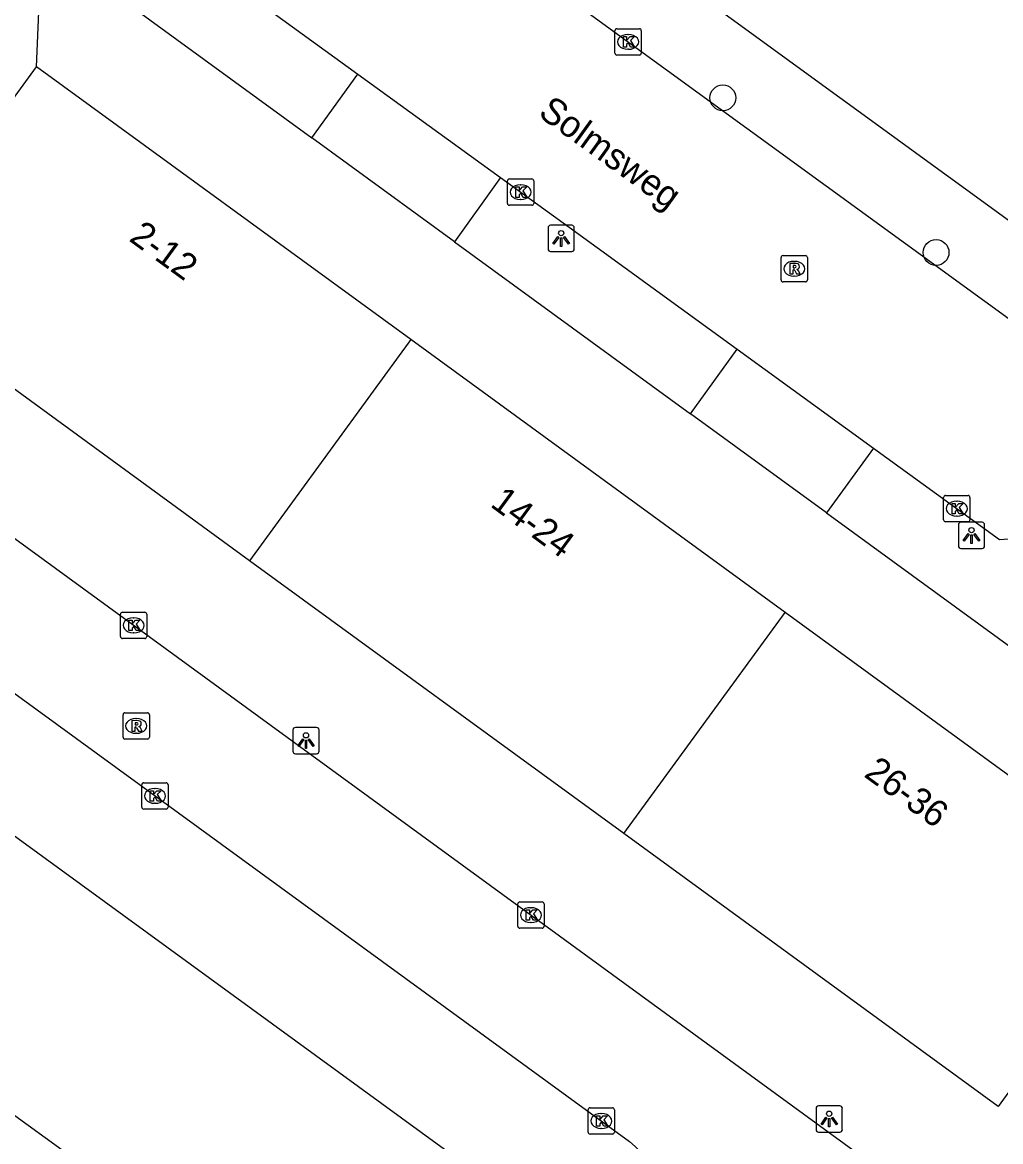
# Model space of a CAD drawing. Extents: x 159675 to 160530, y 382179 to 382901.
# Drawn here: x 160188.71 to 160225.89, y 382395.67 to 382438.2 of the extents above; entities that cross this region are included whole.
import ezdxf

# ---------------------------------------------------------------- set-up
doc = ezdxf.new("R2010")
doc.units = 0
for name, color, linetype in [('IMGEO_Boom', 7, 'Continuous'), ('IMGEO_Groenvoorziening', 7, 'Continuous'), ('IMGEO_Kolk', 7, 'Continuous'), ('IMGEO_Lichtpunt', 7, 'Continuous'), ('IMGEO_Openbare_ruimte_label', 7, 'Continuous'), ('IMGEO_Pand', 7, 'Continuous'), ('IMGEO_Pand_nummerreeks', 7, 'Continuous'), ('IMGEO_Rijbaan_lokaal_open', 7, 'Continuous'), ('IMGEO_Rioolput', 7, 'Continuous'), ('IMGEO_Voetpad_open', 7, 'Continuous')]:
    doc.layers.add(name, color=color, linetype=linetype)

msp = doc.modelspace()

# ---------------------------------------------------------------- linework, layer by layer
at = {"layer": 'IMGEO_Boom'}
for centre in [(160215.336, 382435.334), (160223.441, 382429.456)]:
    msp.add_circle(centre, 0.489, dxfattribs=at)
at = {"layer": 'IMGEO_Groenvoorziening'}
msp.add_lwpolyline([(160205.238, 382384.168), (160210.404, 382391.261), (160181.255, 382412.483)], dxfattribs=at)
at = {"layer": 'IMGEO_Kolk'}
for p, q in [((160211.237, 382437.033), (160211.237, 382437.885)), ((160211.312, 382437.959), (160212.164, 382437.959)), ((160212.238, 382437.885), (160212.238, 382437.033)), ((160211.725, 382437.739), (160211.75, 382437.739)), ((160211.748, 382437.179), (160211.723, 382437.179)), ((160212.164, 382436.959), (160211.312, 382436.959)), ((160207.149, 382431.324), (160207.149, 382432.176)), ((160207.224, 382432.25), (160208.076, 382432.25)), ((160207.637, 382432.03), (160207.662, 382432.03)), ((160208.15, 382432.176), (160208.15, 382431.324)), ((160208.076, 382431.25), (160207.224, 382431.25)), ((160207.66, 382431.47), (160207.635, 382431.47)), ((160223.728, 382419.297), (160223.728, 382420.149)), ((160223.803, 382420.223), (160224.655, 382420.223)), ((160224.729, 382420.149), (160224.729, 382419.297)), ((160224.216, 382420.003), (160224.241, 382420.003)), ((160224.655, 382419.223), (160223.803, 382419.223)), ((160224.239, 382419.443), (160224.214, 382419.443)), ((160192.517, 382415.789), (160193.369, 382415.789)), ((160192.442, 382414.863), (160192.442, 382415.715)), ((160192.93, 382415.569), (160192.955, 382415.569)), ((160193.443, 382415.715), (160193.443, 382414.863)), ((160192.953, 382415.009), (160192.928, 382415.009)), ((160193.369, 382414.789), (160192.517, 382414.789)), ((160193.251, 382408.38), (160193.251, 382409.232)), ((160193.326, 382409.306), (160194.178, 382409.306)), ((160193.739, 382409.086), (160193.764, 382409.086)), ((160194.252, 382409.232), (160194.252, 382408.38)), ((160194.178, 382408.306), (160193.326, 382408.306)), ((160193.762, 382408.526), (160193.737, 382408.526)), ((160207.619, 382404.78), (160208.471, 382404.78)), ((160207.544, 382403.854), (160207.544, 382404.706)), ((160208.032, 382404.56), (160208.057, 382404.56)), ((160208.545, 382404.706), (160208.545, 382403.854)), ((160208.055, 382404), (160208.03, 382404)), ((160208.471, 382403.78), (160207.619, 382403.78)), ((160210.216, 382396.029), (160210.216, 382396.881)), ((160210.291, 382396.955), (160211.143, 382396.955)), ((160210.704, 382396.735), (160210.729, 382396.735)), ((160211.217, 382396.881), (160211.217, 382396.029)), ((160211.143, 382395.955), (160210.291, 382395.955)), ((160210.727, 382396.175), (160210.702, 382396.175))]:
    msp.add_line(p, q, dxfattribs=at)
for points in [[(160211.237, 382437.033), (160211.237, 382437.885)], [(160211.312, 382437.959), (160212.164, 382437.959)], [(160212.238, 382437.885), (160212.238, 382437.033)], [(160211.558, 382437.659), (160211.681, 382437.659), (160211.681, 382437.508), (160211.811, 382437.659), (160211.975, 382437.659), (160211.829, 382437.508), (160211.982, 382437.259), (160211.83, 382437.259), (160211.745, 382437.423), (160211.681, 382437.356), (160211.681, 382437.259), (160211.558, 382437.259), (160211.558, 382437.659)], [(160212.164, 382436.959), (160211.312, 382436.959)], [(160207.149, 382431.324), (160207.149, 382432.176)], [(160207.224, 382432.25), (160208.076, 382432.25)], [(160207.47, 382431.95), (160207.593, 382431.95), (160207.593, 382431.799), (160207.723, 382431.95), (160207.887, 382431.95), (160207.741, 382431.799), (160207.894, 382431.55), (160207.742, 382431.55), (160207.657, 382431.714), (160207.593, 382431.647), (160207.593, 382431.55), (160207.47, 382431.55), (160207.47, 382431.95)], [(160208.15, 382432.176), (160208.15, 382431.324)], [(160208.076, 382431.25), (160207.224, 382431.25)], [(160223.728, 382419.297), (160223.728, 382420.149)], [(160223.803, 382420.223), (160224.655, 382420.223)], [(160224.729, 382420.149), (160224.729, 382419.297)], [(160224.049, 382419.923), (160224.172, 382419.923), (160224.172, 382419.772), (160224.302, 382419.923), (160224.466, 382419.923), (160224.32, 382419.772), (160224.473, 382419.523), (160224.321, 382419.523), (160224.236, 382419.687), (160224.172, 382419.62), (160224.172, 382419.523), (160224.049, 382419.523), (160224.049, 382419.923)], [(160224.655, 382419.223), (160223.803, 382419.223)], [(160192.517, 382415.789), (160193.369, 382415.789)], [(160192.442, 382414.863), (160192.442, 382415.715)], [(160192.763, 382415.489), (160192.886, 382415.489), (160192.886, 382415.338), (160193.016, 382415.489), (160193.18, 382415.489), (160193.034, 382415.338), (160193.187, 382415.089), (160193.035, 382415.089), (160192.95, 382415.253), (160192.886, 382415.186), (160192.886, 382415.089), (160192.763, 382415.089), (160192.763, 382415.489)], [(160193.443, 382415.715), (160193.443, 382414.863)], [(160193.369, 382414.789), (160192.517, 382414.789)], [(160193.251, 382408.38), (160193.251, 382409.232)], [(160193.326, 382409.306), (160194.178, 382409.306)], [(160193.572, 382409.006), (160193.695, 382409.006), (160193.695, 382408.855), (160193.825, 382409.006), (160193.989, 382409.006), (160193.843, 382408.855), (160193.996, 382408.606), (160193.844, 382408.606), (160193.759, 382408.77), (160193.695, 382408.703), (160193.695, 382408.606), (160193.572, 382408.606), (160193.572, 382409.006)], [(160194.252, 382409.232), (160194.252, 382408.38)], [(160194.178, 382408.306), (160193.326, 382408.306)], [(160207.619, 382404.78), (160208.471, 382404.78)], [(160207.544, 382403.854), (160207.544, 382404.706)], [(160207.865, 382404.48), (160207.988, 382404.48), (160207.988, 382404.329), (160208.118, 382404.48), (160208.282, 382404.48), (160208.136, 382404.329), (160208.289, 382404.08), (160208.137, 382404.08), (160208.052, 382404.244), (160207.988, 382404.177), (160207.988, 382404.08), (160207.865, 382404.08), (160207.865, 382404.48)], [(160208.545, 382404.706), (160208.545, 382403.854)], [(160208.471, 382403.78), (160207.619, 382403.78)], [(160210.216, 382396.029), (160210.216, 382396.881)], [(160210.291, 382396.955), (160211.143, 382396.955)], [(160210.537, 382396.655), (160210.66, 382396.655), (160210.66, 382396.504), (160210.79, 382396.655), (160210.954, 382396.655), (160210.808, 382396.504), (160210.961, 382396.255), (160210.809, 382396.255), (160210.724, 382396.419), (160210.66, 382396.352), (160210.66, 382396.255), (160210.537, 382396.255), (160210.537, 382396.655)], [(160211.217, 382396.881), (160211.217, 382396.029)], [(160211.143, 382395.955), (160210.291, 382395.955)]]:
    msp.add_lwpolyline(points, dxfattribs=at)
for centre, start, end in [((160211.314, 382437.883), 91.552, 178.448), ((160211.314, 382437.883), 91.552, 178.448), ((160212.162, 382437.883), 1.552, 88.448), ((160212.162, 382437.883), 1.552, 88.448), ((160211.314, 382437.035), 181.552, 268.448), ((160211.314, 382437.035), 181.552, 268.448), ((160212.162, 382437.035), 271.552, 358.448), ((160212.162, 382437.035), 271.552, 358.448), ((160207.226, 382432.174), 91.552, 178.448), ((160207.226, 382432.174), 91.552, 178.448), ((160208.074, 382432.174), 1.552, 88.448), ((160208.074, 382432.174), 1.552, 88.448), ((160207.226, 382431.326), 181.552, 268.448), ((160207.226, 382431.326), 181.552, 268.448), ((160208.074, 382431.326), 271.552, 358.448), ((160208.074, 382431.326), 271.552, 358.448), ((160223.805, 382420.147), 91.552, 178.448), ((160223.805, 382420.147), 91.552, 178.448), ((160224.653, 382420.147), 1.552, 88.448), ((160224.653, 382420.147), 1.552, 88.448), ((160223.805, 382419.299), 181.552, 268.448), ((160223.805, 382419.299), 181.552, 268.448), ((160224.653, 382419.299), 271.552, 358.448), ((160224.653, 382419.299), 271.552, 358.448), ((160192.519, 382415.713), 91.552, 178.448), ((160192.519, 382415.713), 91.552, 178.448), ((160193.367, 382415.713), 1.552, 88.448), ((160193.367, 382415.713), 1.552, 88.448), ((160192.519, 382414.865), 181.552, 268.448), ((160192.519, 382414.865), 181.552, 268.448), ((160193.367, 382414.865), 271.552, 358.448), ((160193.367, 382414.865), 271.552, 358.448), ((160193.328, 382409.23), 91.552, 178.448), ((160193.328, 382409.23), 91.552, 178.448), ((160194.176, 382409.23), 1.552, 88.448), ((160194.176, 382409.23), 1.552, 88.448), ((160193.328, 382408.382), 181.552, 268.448), ((160193.328, 382408.382), 181.552, 268.448), ((160194.176, 382408.382), 271.552, 358.448), ((160194.176, 382408.382), 271.552, 358.448), ((160207.621, 382404.704), 91.552, 178.448), ((160207.621, 382404.704), 91.552, 178.448), ((160208.469, 382404.704), 1.552, 88.448), ((160208.469, 382404.704), 1.552, 88.448), ((160207.621, 382403.856), 181.552, 268.448), ((160207.621, 382403.856), 181.552, 268.448), ((160208.469, 382403.856), 271.552, 358.448), ((160208.469, 382403.856), 271.552, 358.448), ((160210.293, 382396.879), 91.552, 178.448), ((160210.293, 382396.879), 91.552, 178.448), ((160211.141, 382396.879), 1.552, 88.448), ((160211.141, 382396.879), 1.552, 88.448), ((160210.293, 382396.031), 181.552, 268.448), ((160210.293, 382396.031), 181.552, 268.448), ((160211.141, 382396.031), 271.552, 358.448), ((160211.141, 382396.031), 271.552, 358.448)]:
    msp.add_arc(centre, 0.0765, start, end, dxfattribs=at)
for centre, major_axis, ratio, start_param, end_param in [((160211.724, 382437.459), (-0.387, 0.002), 0.722429, 4.712389, 7.853982), ((160211.749, 382437.459), (-0.39, 0.002), 0.717154, 1.570796, 4.712389), ((160207.636, 382431.75), (-0.387, 0.002), 0.722429, 4.712389, 7.853982), ((160207.661, 382431.75), (-0.39, 0.002), 0.717154, 1.570796, 4.712389), ((160224.215, 382419.723), (-0.387, 0.002), 0.722429, 4.712389, 7.853982), ((160224.24, 382419.723), (-0.39, 0.002), 0.717154, 1.570796, 4.712389), ((160192.929, 382415.289), (-0.387, 0.002), 0.722429, 4.712389, 7.853982), ((160192.954, 382415.289), (-0.39, 0.002), 0.717154, 1.570796, 4.712389), ((160193.738, 382408.806), (-0.387, 0.002), 0.722429, 4.712389, 7.853982), ((160193.763, 382408.806), (-0.39, 0.002), 0.717154, 1.570796, 4.712389), ((160208.031, 382404.28), (-0.387, 0.002), 0.722429, 4.712389, 7.853982), ((160208.056, 382404.28), (-0.39, 0.002), 0.717154, 1.570796, 4.712389), ((160210.703, 382396.455), (-0.387, 0.002), 0.722429, 4.712389, 7.853982), ((160210.728, 382396.455), (-0.39, 0.002), 0.717154, 1.570796, 4.712389)]:
    msp.add_ellipse(centre, major_axis=major_axis, ratio=ratio, start_param=start_param, end_param=end_param, dxfattribs=at)
at = {"layer": 'IMGEO_Lichtpunt'}
for p, q in [((160208.694, 382430.396), (160208.694, 382429.589)), ((160208.694, 382430.396), (160208.694, 382429.589)), ((160209.596, 382430.491), (160208.788, 382430.491)), ((160209.596, 382430.491), (160208.788, 382430.491)), ((160209.69, 382429.589), (160209.69, 382430.396)), ((160209.69, 382429.589), (160209.69, 382430.396)), ((160208.788, 382429.495), (160209.596, 382429.495)), ((160208.788, 382429.495), (160209.596, 382429.495)), ((160225.19, 382419.205), (160224.382, 382419.205)), ((160225.19, 382419.205), (160224.382, 382419.205)), ((160224.288, 382419.11), (160224.288, 382418.303)), ((160224.288, 382419.11), (160224.288, 382418.303)), ((160225.284, 382418.303), (160225.284, 382419.11)), ((160225.284, 382418.303), (160225.284, 382419.11)), ((160224.382, 382418.209), (160225.19, 382418.209)), ((160224.382, 382418.209), (160225.19, 382418.209)), ((160198.995, 382411.313), (160198.995, 382410.506)), ((160198.995, 382411.313), (160198.995, 382410.506)), ((160199.897, 382411.408), (160199.089, 382411.408)), ((160199.897, 382411.408), (160199.089, 382411.408)), ((160199.991, 382410.506), (160199.991, 382411.313)), ((160199.991, 382410.506), (160199.991, 382411.313)), ((160199.089, 382410.412), (160199.897, 382410.412)), ((160199.089, 382410.412), (160199.897, 382410.412)), ((160218.882, 382396.933), (160218.882, 382396.126)), ((160218.882, 382396.933), (160218.882, 382396.126)), ((160219.784, 382397.028), (160218.976, 382397.028)), ((160219.784, 382397.028), (160218.976, 382397.028)), ((160219.878, 382396.126), (160219.878, 382396.933)), ((160219.878, 382396.126), (160219.878, 382396.933)), ((160218.976, 382396.032), (160219.784, 382396.032)), ((160218.976, 382396.032), (160219.784, 382396.032))]:
    msp.add_line(p, q, dxfattribs=at)
for points in [[(160209.068, 382430.06), (160209.107, 382430.032), (160208.919, 382429.77), (160208.881, 382429.797), (160209.068, 382430.06)], [(160209.17, 382430.012), (160209.217, 382430.012), (160209.217, 382429.69), (160209.17, 382429.69), (160209.17, 382430.012)], [(160209.28, 382430.032), (160209.318, 382430.059), (160209.505, 382429.797), (160209.466, 382429.769), (160209.28, 382430.032)], [(160224.662, 382418.774), (160224.701, 382418.746), (160224.513, 382418.484), (160224.475, 382418.511), (160224.662, 382418.774)], [(160224.874, 382418.746), (160224.912, 382418.773), (160225.099, 382418.511), (160225.06, 382418.483), (160224.874, 382418.746)], [(160224.764, 382418.726), (160224.811, 382418.726), (160224.811, 382418.404), (160224.764, 382418.404), (160224.764, 382418.726)], [(160199.369, 382410.977), (160199.408, 382410.949), (160199.22, 382410.687), (160199.182, 382410.714), (160199.369, 382410.977)], [(160199.471, 382410.929), (160199.518, 382410.929), (160199.518, 382410.607), (160199.471, 382410.607), (160199.471, 382410.929)], [(160199.581, 382410.949), (160199.619, 382410.976), (160199.806, 382410.714), (160199.767, 382410.686), (160199.581, 382410.949)], [(160219.256, 382396.597), (160219.295, 382396.569), (160219.107, 382396.307), (160219.069, 382396.334), (160219.256, 382396.597)], [(160219.358, 382396.549), (160219.405, 382396.549), (160219.405, 382396.227), (160219.358, 382396.227), (160219.358, 382396.549)], [(160219.468, 382396.569), (160219.506, 382396.596), (160219.693, 382396.334), (160219.654, 382396.306), (160219.468, 382396.569)]]:
    msp.add_lwpolyline(points, dxfattribs=at)
for centre in [(160209.193, 382430.194), (160224.787, 382418.908), (160199.494, 382411.111), (160219.381, 382396.731)]:
    msp.add_circle(centre, 0.0994, dxfattribs=at)
for centre, start, end in [((160208.788, 382430.396), 90, 180), ((160208.788, 382430.396), 90, 180), ((160209.596, 382430.396), 0, 90), ((160209.596, 382430.396), 0, 90), ((160208.788, 382429.589), 180, 270), ((160208.788, 382429.589), 180, 270), ((160209.596, 382429.589), 270, 0), ((160209.596, 382429.589), 270, 360), ((160224.382, 382419.11), 90, 180), ((160224.382, 382419.11), 90, 180), ((160225.19, 382419.11), 0, 90), ((160225.19, 382419.11), 0, 90), ((160224.382, 382418.303), 180, 270), ((160224.382, 382418.303), 180, 270), ((160225.19, 382418.303), 270, 0), ((160225.19, 382418.303), 270, 360), ((160199.089, 382411.313), 90, 180), ((160199.089, 382411.313), 90, 180), ((160199.897, 382411.313), 0, 90), ((160199.897, 382411.313), 0, 90), ((160199.089, 382410.506), 180, 270), ((160199.089, 382410.506), 180, 270), ((160199.897, 382410.506), 270, 0), ((160199.897, 382410.506), 270, 360), ((160218.976, 382396.933), 90, 180), ((160218.976, 382396.933), 90, 180), ((160219.784, 382396.933), 0, 90), ((160219.784, 382396.933), 0, 90), ((160218.976, 382396.126), 180, 270), ((160218.976, 382396.126), 180, 270), ((160219.784, 382396.126), 270, 0), ((160219.784, 382396.126), 270, 360)]:
    msp.add_arc(centre, 0.0946, start, end, dxfattribs=at)
at = {"layer": 'IMGEO_Pand'}
for points in [[(160197.35, 382417.743), (160183.127, 382428.11), (160189.255, 382436.517)], [(160203.478, 382426.15), (160189.255, 382436.517)], [(160203.478, 382426.15), (160197.35, 382417.743)], [(160217.701, 382415.783), (160203.478, 382426.15)], [(160211.573, 382407.377), (160197.35, 382417.743)], [(160211.573, 382407.377), (160217.701, 382415.783)], [(160231.923, 382405.417), (160217.701, 382415.783)], [(160231.923, 382405.417), (160225.796, 382397.01), (160211.573, 382407.377)], [(160197.474, 382389.807), (160197.609, 382389.993), (160176.874, 382405.028), (160176.749, 382404.856)]]:
    msp.add_lwpolyline(points, dxfattribs=at)
at = {"layer": 'IMGEO_Rijbaan_lokaal_open'}
for points in [[(160246.396, 382412.259), (160195.141, 382449.525)], [(160190.801, 382443.973), (160201.47, 382436.234)], [(160201.47, 382436.234), (160206.885, 382432.306)], [(160206.885, 382432.306), (160209.493, 382430.414), (160215.878, 382425.783)], [(160178.065, 382426.137), (160223.044, 382393.348), (160187.51, 382344.568), (160186.917, 382344.985)], [(160215.878, 382425.783), (160221.062, 382422.022)], [(160221.062, 382422.022), (160225.848, 382418.551), (160228.002, 382418.705)], [(160183.748, 382416.088), (160211.791, 382395.671)]]:
    msp.add_lwpolyline(points, dxfattribs=at)
msp.add_arc((160207.97, 382391.098), 5.959, 327.9705, 50.1193, dxfattribs=at)
at = {"layer": 'IMGEO_Rioolput'}
for p, q in [((160217.549, 382428.414), (160217.549, 382429.266)), ((160217.624, 382429.34), (160218.476, 382429.34)), ((160218.037, 382429.12), (160218.062, 382429.12)), ((160218.55, 382429.266), (160218.55, 382428.414)), ((160218.06, 382428.56), (160218.035, 382428.56)), ((160218.476, 382428.34), (160217.624, 382428.34)), ((160192.614, 382411.967), (160193.466, 382411.967)), ((160192.539, 382411.041), (160192.539, 382411.893)), ((160193.027, 382411.747), (160193.052, 382411.747)), ((160193.54, 382411.893), (160193.54, 382411.041)), ((160193.05, 382411.187), (160193.025, 382411.187)), ((160193.466, 382410.967), (160192.614, 382410.967))]:
    msp.add_line(p, q, dxfattribs=at)
for points in [[(160217.549, 382428.414), (160217.549, 382429.266)], [(160217.624, 382429.34), (160218.476, 382429.34)], [(160218.138, 382429.038), (160217.886, 382429.04), (160217.886, 382428.64)], [(160218.064, 382428.959), (160218.01, 382428.959), (160218.01, 382428.878)], [(160218.55, 382429.266), (160218.55, 382428.414)], [(160217.886, 382428.64), (160218.01, 382428.64), (160218.01, 382428.802), (160218.021, 382428.802)], [(160218.01, 382428.878), (160218.062, 382428.878)], [(160218.068, 382428.773), (160218.139, 382428.64), (160218.279, 382428.64), (160218.214, 382428.766)], [(160218.476, 382428.34), (160217.624, 382428.34)], [(160192.614, 382411.967), (160193.466, 382411.967)], [(160192.539, 382411.041), (160192.539, 382411.893)], [(160193.128, 382411.665), (160192.876, 382411.667), (160192.876, 382411.267)], [(160193.054, 382411.586), (160193, 382411.586), (160193, 382411.505)], [(160193.54, 382411.893), (160193.54, 382411.041)], [(160192.876, 382411.267), (160193, 382411.267), (160193, 382411.429), (160193.011, 382411.429)], [(160193, 382411.505), (160193.052, 382411.505)], [(160193.058, 382411.4), (160193.129, 382411.267), (160193.269, 382411.267), (160193.204, 382411.393)], [(160193.466, 382410.967), (160192.614, 382410.967)]]:
    msp.add_lwpolyline(points, dxfattribs=at)
for centre, radius, start, end in [((160217.626, 382429.264), 0.0765, 91.552, 178.448), ((160217.626, 382429.264), 0.0765, 91.552, 178.448), ((160218.07, 382428.863), 0.0964, 77.0061, 93.1865), ((160218.084, 382428.92), 0.0378, 276.6634, 79.6772), ((160218.137, 382428.928), 0.109, 350.3612, 89.416), ((160218.474, 382429.264), 0.0765, 1.552, 88.448), ((160218.474, 382429.264), 0.0765, 1.552, 88.448), ((160218.02, 382428.749), 0.0533, 26.0293, 88.6989), ((160218.046, 382429.067), 0.19, 274.7715, 282.9687), ((160218.135, 382428.928), 0.112, 277.5842, 350.9817), ((160218.119, 382428.713), 0.108, 29.5134, 73.7905), ((160217.626, 382428.416), 0.0765, 181.552, 268.448), ((160217.626, 382428.416), 0.0765, 181.552, 268.448), ((160218.474, 382428.416), 0.0765, 271.552, 358.448), ((160218.474, 382428.416), 0.0765, 271.552, 358.448), ((160192.616, 382411.891), 0.0765, 91.552, 178.448), ((160192.616, 382411.891), 0.0765, 91.552, 178.448), ((160193.464, 382411.891), 0.0765, 1.552, 88.448), ((160193.464, 382411.891), 0.0765, 1.552, 88.448), ((160193.06, 382411.49), 0.0964, 77.0061, 93.1865), ((160193.074, 382411.547), 0.0378, 276.6634, 79.6772), ((160193.127, 382411.555), 0.109, 350.3612, 89.416), ((160193.125, 382411.555), 0.112, 277.5842, 350.9817), ((160193.01, 382411.376), 0.0533, 26.0293, 88.6989), ((160193.036, 382411.694), 0.19, 274.7715, 282.9687), ((160193.109, 382411.34), 0.108, 29.5134, 73.7905), ((160192.616, 382411.043), 0.0765, 181.552, 268.448), ((160192.616, 382411.043), 0.0765, 181.552, 268.448), ((160193.464, 382411.043), 0.0765, 271.552, 358.448), ((160193.464, 382411.043), 0.0765, 271.552, 358.448)]:
    msp.add_arc(centre, radius, start, end, dxfattribs=at)
for centre, major_axis, ratio, start_param, end_param in [((160218.036, 382428.84), (-0.387, 0.002), 0.722429, 4.712389, 7.853982), ((160218.061, 382428.84), (-0.39, 0.002), 0.717154, 1.570796, 4.712389), ((160193.026, 382411.467), (-0.387, 0.002), 0.722429, 4.712389, 7.853982), ((160193.051, 382411.467), (-0.39, 0.002), 0.717154, 1.570796, 4.712389)]:
    msp.add_ellipse(centre, major_axis=major_axis, ratio=ratio, start_param=start_param, end_param=end_param, dxfattribs=at)
at = {"layer": 'IMGEO_Voetpad_open'}
for points in [[(160248.967, 382414.122), (160207.256, 382444.449)], [(160189.255, 382436.517), (160189.455, 382441.296)], [(160189.455, 382441.296), (160199.721, 382433.813)], [(160199.721, 382433.813), (160201.47, 382436.234)], [(160205.134, 382429.868), (160199.721, 382433.813)], [(160206.885, 382432.306), (160205.134, 382429.868)], [(160205.134, 382429.868), (160214.103, 382423.331)], [(160214.103, 382423.331), (160215.878, 382425.783)], [(160219.275, 382419.561), (160214.103, 382423.331)], [(160221.062, 382422.022), (160219.275, 382419.561)], [(160219.275, 382419.561), (160228.331, 382412.96)]]:
    msp.add_lwpolyline(points, dxfattribs=at)

# ---------------------------------------------------------------- texts
at = {"layer": 'IMGEO_Openbare_ruimte_label'}
msp.add_text('Solmsweg', height=1, rotation=324.1959, dxfattribs=at).set_placement((160208.275, 382434.662))
at = {"layer": 'IMGEO_Pand_nummerreeks'}
for s, rotation, p in [('2-12', 323.9123, (160192.73, 382429.925)), ('14-24', 323.6081, (160206.458, 382419.832)), ('26-36', 323.9123, (160220.661, 382409.567))]:
    msp.add_text(s, height=1, rotation=rotation, dxfattribs=at).set_placement(p)

doc.saveas('drawing.dxf')
